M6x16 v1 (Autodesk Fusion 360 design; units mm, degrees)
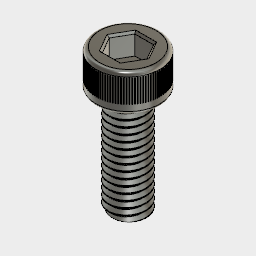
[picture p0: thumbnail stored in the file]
sketch "スケッチ1"
  circle C1 centre (0, 0) radius 3
  circle C2 centre (0, 0) radius 5
  dimension "d1" diameter C1 = 6
  dimension "d2" diameter C2 = 10
extrude "押し出し1" new body sketch "スケッチ1" blind 5.8
sketch "スケッチ2" plane through (0, 0, 5.8) normal (0, 0, 1) x axis (-1, 0, 0)
  line L1 (-1.4722, -2.55) -> (-2.9445, 0)
  line L2 (1.4722, -2.55) -> (-1.4722, -2.55)
  line L3 (2.9445, 0) -> (1.4722, -2.55)
  line L4 (1.4722, 2.55) -> (2.9445, 0)
  line L5 (-1.4722, 2.55) -> (1.4722, 2.55)
  line L6 (-2.9445, 0) -> (-1.4722, 2.55)
  circle C1 centre (0, 0) radius 5
  dimension "d5" distance L2 L5 = 5.1
work_plane "作業平面" sketch "スケッチ2" AlongDistance -0.75
extrude "押し出し2" cut sketch "スケッチ2" profile of L1 L2 L3 L4 L5 L6 against normal blind 3.3
chamfer "面取り" distance 0.3
sketch "スケッチ3" plane through (0, 0, 5.05) normal (0, 0, 1) x axis (1, 0, 0)
  line L1 (-0.05, 4.9497) -> (-0.05, 4.9997)
  line L2 (0.05, 4.9497) -> (-0.05, 4.9497)
  line L3 (0.05, 4.9997) -> (0.05, 4.9497)
  circle C1 centre (0, 0) radius 5
  point P4 (-0.05, 4.9497)
  point P5 (0.05, 4.9497)
  point P3 (-0.05, 4.9997)
  point P6 (0.05, 4.9997)
  dimension "d18" distance P4 P5 = 0.1
  dimension "d19" distance P3 P4 = 0.05
  dimension "d20" distance P5 P6 = 0.05 (= "d19")
extrude "押し出し3" cut sketch "スケッチ3" against normal blind 3.6
work_axis "作業軸"
circular_pattern "C パターン" countU 100 TotalAngle 360
fillet "フィレット1" radius 0.6
extrude "押し出し4" add sketch "スケッチ1" profile of C1 blind -16
thread "ねじ"
fillet "フィレット2" sketch "スケッチ3" radius 0.5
